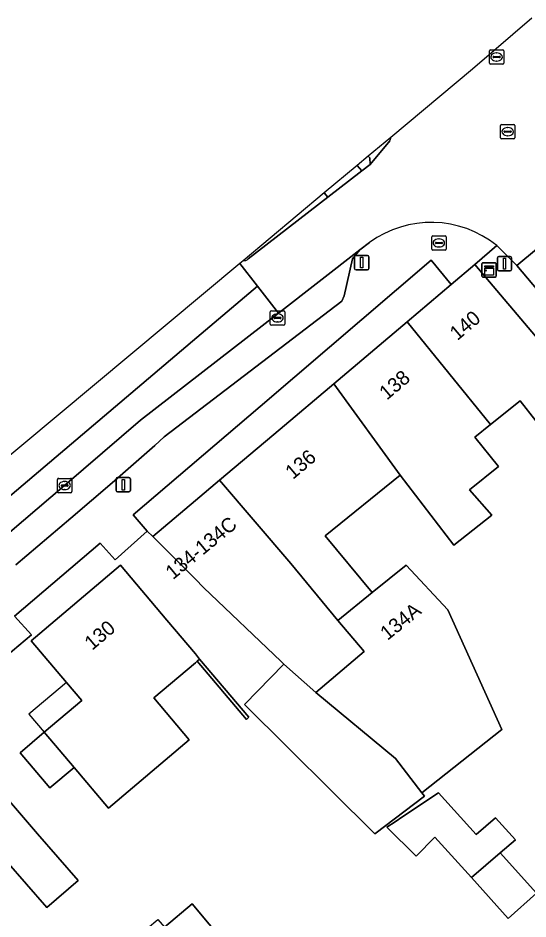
# Model space of a CAD drawing. Extents: x 162172 to 163187, y 382874 to 383685.
# Drawn here: x 162487.7 to 162523.1, y 383338.9 to 383401.6 of the extents above; entities that cross this region are included whole.
import ezdxf

# ---------------------------------------------------------------- set-up
doc = ezdxf.new("R2010")
doc.units = 0
for name, color, linetype in [('IMGEO_Brandkraan', 7, 'Continuous'), ('IMGEO_Erf', 7, 'Continuous'), ('IMGEO_Kast', 7, 'Continuous'), ('IMGEO_Kolk', 7, 'Continuous'), ('IMGEO_Lichtmast', 7, 'Continuous'), ('IMGEO_Muur', 7, 'Continuous'), ('IMGEO_Pand', 7, 'Continuous'), ('IMGEO_Pand_nummerreeks', 7, 'Continuous'), ('IMGEO_Pand_overbouw', 7, 'Continuous'), ('IMGEO_Parkeervlak_open', 7, 'Continuous'), ('IMGEO_Rijbaan_lokaal_gesloten', 7, 'Continuous'), ('IMGEO_Rioolput', 7, 'Continuous'), ('IMGEO_Verkeerseiland_gesloten', 7, 'Continuous'), ('IMGEO_Verkeerseiland_open', 7, 'Continuous'), ('IMGEO_Voetpad_open', 7, 'Continuous')]:
    doc.layers.add(name, color=color, linetype=linetype)

msp = doc.modelspace()

# ---------------------------------------------------------------- linework, layer by layer
at = {"layer": 'IMGEO_Brandkraan'}
for p, q in [((162516.501, 383386.413), (162517.353, 383386.413)), ((162516.426, 383385.487), (162516.426, 383386.339)), ((162516.685, 383385.907), (162516.685, 383385.919)), ((162517.123, 383385.87), (162516.725, 383385.87)), ((162516.728, 383385.956), (162517.126, 383385.956)), ((162516.914, 383386.193), (162516.939, 383386.193)), ((162517.169, 383385.919), (162517.169, 383385.907)), ((162517.427, 383386.339), (162517.427, 383385.487)), ((162517.353, 383385.413), (162516.501, 383385.413)), ((162516.937, 383385.633), (162516.912, 383385.633))]:
    msp.add_line(p, q, dxfattribs=at)
for points in [[(162516.501, 383386.413), (162517.353, 383386.413)], [(162516.426, 383385.487), (162516.426, 383386.339)], [(162517.427, 383386.339), (162517.427, 383385.487)], [(162517.353, 383385.413), (162516.501, 383385.413)]]:
    msp.add_lwpolyline(points, dxfattribs=at)
for centre, radius, start, end in [((162516.503, 383386.337), 0.0765, 91.55205, 178.44795), ((162516.503, 383386.337), 0.0765, 91.55205, 178.44795), ((162517.351, 383386.337), 0.0765, 1.55205, 88.44795), ((162517.351, 383386.337), 0.0765, 1.55205, 88.44795), ((162516.725, 383385.916), 0.0403, 85.87752, 175.75265), ((162516.722, 383385.906), 0.0366, 178.93798, 274.71019), ((162517.126, 383385.913), 0.043, 264.86636, 352.45326), ((162517.13, 383385.918), 0.0386, 1.73085, 96.63898), ((162516.503, 383385.489), 0.0765, 181.55205, 268.44795), ((162516.503, 383385.489), 0.0765, 181.55205, 268.44795), ((162517.351, 383385.489), 0.0765, 271.55205, 358.44795), ((162517.351, 383385.489), 0.0765, 271.55205, 358.44795)]:
    msp.add_arc(centre, radius, start, end, dxfattribs=at)
for centre, major_axis, ratio, start_param, end_param in [((162516.913, 383385.913), (-0.387, 0.002), 0.722429, 4.712389, 7.853982), ((162516.938, 383385.913), (-0.39, 0.002), 0.717154, 1.570796, 4.712389)]:
    msp.add_ellipse(centre, major_axis=major_axis, ratio=ratio, start_param=start_param, end_param=end_param, dxfattribs=at)
at = {"layer": 'IMGEO_Erf'}
for points in [[(162514.719, 383380.429), (162517.788, 383383.021), (162516.381, 383384.728), (162504.504, 383374.543), (162495.688, 383367.015), (162496.66, 383365.876), (162497.039, 383365.491), (162500, 383367.993), (162501.673, 383369.406), (162505.887, 383372.966), (162509.628, 383376.127)], [(162493.954, 383346.606), (162491.568, 383349.429), (162489.89, 383348.011), (162487.823, 383350.458), (162489.498, 383351.878), (162492.105, 383354.084), (162491.038, 383355.349), (162488.584, 383358.252), (162494.787, 383363.495), (162498.015, 383359.676), (162500, 383357.328), (162500.298, 383356.976), (162503.724, 383352.923), (162503.551, 383352.777), (162500.125, 383356.829), (162500, 383356.723), (162497.117, 383354.277), (162499.58, 383351.362)], [(162519.187, 383341.776), (162516.653, 383344.592), (162515.348, 383343.264), (162513.305, 383345.272), (162513.885, 383345.659), (162514.422, 383346.017), (162516.899, 383347.669), (162519.508, 383344.771), (162520.866, 383345.939), (162522.244, 383344.408), (162521.184, 383343.495), (162523.7, 383340.699), (162521.742, 383338.937)], [(162500.266, 383335.557), (162500.462, 383335.333), (162497.535, 383332.877), (162494.528, 383336.46), (162497.382, 383338.856), (162497.848, 383338.323), (162499.778, 383339.943), (162502.141, 383337.128)]]:
    msp.add_lwpolyline(points, close=True, dxfattribs=at)
for points in [[(162525.842, 383370.767), (162522.567, 383374.937), (162520.525, 383373.288), (162519.423, 383372.398), (162521.073, 383370.369), (162519.047, 383368.745), (162520.601, 383366.992), (162517.97, 383364.884), (162514.245, 383369.761), (162509.032, 383365.553), (162512.296, 383361.595), (162514.663, 383363.508), (162517.538, 383360.406), (162521.291, 383352.065), (162515.743, 383347.675), (162515.922, 383347.439), (162512.471, 383344.81), (162503.422, 383353.804), (162506.151, 383356.625), (162505.974, 383356.794), (162500.574, 383361.955), (162500, 383362.529), (162497.039, 383365.491), (162496.66, 383365.876), (162494.431, 383363.864), (162493.381, 383365.045), (162487.439, 383359.96), (162488.604, 383358.667), (162484.189, 383354.943)], [(162485.394, 383349.029), (162489.031, 383344.825), (162491.847, 383341.571), (162489.669, 383339.685), (162486.852, 383342.939)]]:
    msp.add_lwpolyline(points, dxfattribs=at)
at = {"layer": 'IMGEO_Kast'}
for p, q in [((162519.992, 383384.536), (162520.833, 383384.536)), ((162520.833, 383384.536), (162519.992, 383384.536)), ((162519.917, 383383.611), (162519.917, 383384.452)), ((162519.917, 383384.452), (162519.917, 383383.611)), ((162520.917, 383384.461), (162520.917, 383383.62)), ((162520.917, 383383.62), (162520.917, 383384.461)), ((162520.842, 383383.536), (162520.001, 383383.536)), ((162520.001, 383383.536), (162520.842, 383383.536))]:
    msp.add_line(p, q, dxfattribs=at)
for points in [[(162520.112, 383384.326), (162520.712, 383384.326), (162520.712, 383384.241), (162520.112, 383384.241), (162520.112, 383384.326)], [(162520.112, 383384.151), (162520.712, 383384.151), (162520.712, 383383.662), (162520.112, 383383.662), (162520.112, 383384.151)]]:
    msp.add_lwpolyline(points, dxfattribs=at)
msp.add_circle((162520.196, 383384), 0.0377, dxfattribs=at)
for centre, start, end in [((162519.995, 383384.458), 92.4484, 184.28452), ((162519.995, 383384.458), 92.4484, 184.28452), ((162520.839, 383384.458), 2.4484, 94.28452), ((162520.839, 383384.458), 2.4484, 94.28452), ((162519.995, 383383.614), 182.4484, 274.28452), ((162519.995, 383383.614), 182.4484, 274.28452), ((162520.839, 383383.614), 272.4484, 4.28452), ((162520.839, 383383.614), 272.4484, 4.28452)]:
    msp.add_arc(centre, 0.0779, start, end, dxfattribs=at)
at = {"layer": 'IMGEO_Kolk'}
for p, q in [((162505.208, 383380.274), (162505.208, 383381.126)), ((162505.283, 383381.2), (162506.135, 383381.2)), ((162505.51, 383380.743), (162505.908, 383380.743)), ((162505.696, 383380.98), (162505.721, 383380.98)), ((162506.209, 383381.126), (162506.209, 383380.274)), ((162506.135, 383380.2), (162505.283, 383380.2)), ((162505.467, 383380.694), (162505.467, 383380.706)), ((162505.905, 383380.657), (162505.507, 383380.657)), ((162505.719, 383380.42), (162505.694, 383380.42)), ((162505.951, 383380.706), (162505.951, 383380.694)), ((162490.414, 383368.617), (162490.414, 383369.469)), ((162490.489, 383369.543), (162491.341, 383369.543)), ((162491.415, 383369.469), (162491.415, 383368.617)), ((162490.673, 383369.037), (162490.673, 383369.049)), ((162491.111, 383369), (162490.713, 383369)), ((162490.716, 383369.086), (162491.114, 383369.086)), ((162490.902, 383369.323), (162490.927, 383369.323)), ((162491.157, 383369.049), (162491.157, 383369.037)), ((162491.341, 383368.543), (162490.489, 383368.543)), ((162490.925, 383368.763), (162490.9, 383368.763))]:
    msp.add_line(p, q, dxfattribs=at)
for points in [[(162505.208, 383380.274), (162505.208, 383381.126)], [(162505.283, 383381.2), (162506.135, 383381.2)], [(162506.209, 383381.126), (162506.209, 383380.274)], [(162506.135, 383380.2), (162505.283, 383380.2)], [(162490.414, 383368.617), (162490.414, 383369.469)], [(162490.489, 383369.543), (162491.341, 383369.543)], [(162491.415, 383369.469), (162491.415, 383368.617)], [(162491.341, 383368.543), (162490.489, 383368.543)]]:
    msp.add_lwpolyline(points, dxfattribs=at)
for centre, radius, start, end in [((162505.285, 383381.124), 0.0765, 91.55205, 178.44795), ((162505.285, 383381.124), 0.0765, 91.55205, 178.44795), ((162505.507, 383380.703), 0.0403, 85.87752, 175.75265), ((162505.912, 383380.705), 0.0386, 1.73085, 96.63898), ((162506.133, 383381.124), 0.0765, 1.55205, 88.44795), ((162506.133, 383381.124), 0.0765, 1.55205, 88.44795), ((162505.285, 383380.276), 0.0765, 181.55205, 268.44795), ((162505.285, 383380.276), 0.0765, 181.55205, 268.44795), ((162505.504, 383380.693), 0.0366, 178.93798, 274.71019), ((162505.908, 383380.7), 0.043, 264.86636, 352.45326), ((162506.133, 383380.276), 0.0765, 271.55205, 358.44795), ((162506.133, 383380.276), 0.0765, 271.55205, 358.44795), ((162490.491, 383369.467), 0.0765, 91.55205, 178.44795), ((162490.491, 383369.467), 0.0765, 91.55205, 178.44795), ((162491.339, 383369.467), 0.0765, 1.55205, 88.44795), ((162491.339, 383369.467), 0.0765, 1.55205, 88.44795), ((162490.713, 383369.046), 0.0403, 85.87752, 175.75265), ((162490.71, 383369.036), 0.0366, 178.93798, 274.71019), ((162491.114, 383369.043), 0.043, 264.86636, 352.45326), ((162491.118, 383369.048), 0.0386, 1.73085, 96.63898), ((162490.491, 383368.619), 0.0765, 181.55205, 268.44795), ((162490.491, 383368.619), 0.0765, 181.55205, 268.44795), ((162491.339, 383368.619), 0.0765, 271.55205, 358.44795), ((162491.339, 383368.619), 0.0765, 271.55205, 358.44795)]:
    msp.add_arc(centre, radius, start, end, dxfattribs=at)
for centre, major_axis, ratio, start_param, end_param in [((162505.695, 383380.7), (-0.387, 0.002), 0.722429, 4.712389, 7.853982), ((162505.72, 383380.7), (-0.39, 0.002), 0.717154, 1.570796, 4.712389), ((162490.901, 383369.043), (-0.387, 0.002), 0.722429, 4.712389, 7.853982), ((162490.926, 383369.043), (-0.39, 0.002), 0.717154, 1.570796, 4.712389)]:
    msp.add_ellipse(centre, major_axis=major_axis, ratio=ratio, start_param=start_param, end_param=end_param, dxfattribs=at)
at = {"layer": 'IMGEO_Lichtmast'}
for p, q in [((162511.066, 383384.148), (162511.066, 383384.948)), ((162511.066, 383384.948), (162511.066, 383384.148)), ((162511.166, 383385.048), (162511.956, 383385.048)), ((162511.956, 383385.048), (162511.166, 383385.048)), ((162512.056, 383384.948), (162512.056, 383384.148)), ((162512.056, 383384.148), (162512.056, 383384.948)), ((162520.992, 383384.071), (162520.992, 383384.871)), ((162520.992, 383384.871), (162520.992, 383384.071)), ((162521.092, 383384.971), (162521.882, 383384.971)), ((162521.882, 383384.971), (162521.092, 383384.971)), ((162521.982, 383384.871), (162521.982, 383384.071)), ((162521.982, 383384.071), (162521.982, 383384.871)), ((162511.956, 383384.048), (162511.166, 383384.048)), ((162511.166, 383384.048), (162511.956, 383384.048)), ((162521.882, 383383.971), (162521.092, 383383.971)), ((162521.092, 383383.971), (162521.882, 383383.971)), ((162494.494, 383368.697), (162494.494, 383369.497)), ((162494.494, 383369.497), (162494.494, 383368.697)), ((162494.594, 383369.597), (162495.384, 383369.597)), ((162495.384, 383369.597), (162494.594, 383369.597)), ((162495.484, 383369.497), (162495.484, 383368.697)), ((162495.484, 383368.697), (162495.484, 383369.497)), ((162495.384, 383368.597), (162494.594, 383368.597)), ((162494.594, 383368.597), (162495.384, 383368.597))]:
    msp.add_line(p, q, dxfattribs=at)
for points in [[(162511.486, 383384.923), (162511.636, 383384.923), (162511.636, 383384.173), (162511.486, 383384.173), (162511.486, 383384.923)], [(162521.412, 383384.846), (162521.562, 383384.846), (162521.562, 383384.096), (162521.412, 383384.096), (162521.412, 383384.846)], [(162494.914, 383369.472), (162495.064, 383369.472), (162495.064, 383368.722), (162494.914, 383368.722), (162494.914, 383369.472)]]:
    msp.add_lwpolyline(points, dxfattribs=at)
for centre, start, end in [((162511.166, 383384.948), 90, 180), ((162511.166, 383384.948), 90, 180), ((162511.956, 383384.948), 0, 90), ((162511.956, 383384.948), 360, 90), ((162521.092, 383384.871), 90, 180), ((162521.092, 383384.871), 90, 180), ((162521.882, 383384.871), 0, 90), ((162521.882, 383384.871), 360, 90), ((162511.166, 383384.148), 180, 270), ((162511.166, 383384.148), 180, 270), ((162511.956, 383384.148), 270, 0), ((162511.956, 383384.148), 270, 0), ((162521.092, 383384.071), 180, 270), ((162521.092, 383384.071), 180, 270), ((162521.882, 383384.071), 270, 0), ((162521.882, 383384.071), 270, 0), ((162494.594, 383369.497), 90, 180), ((162494.594, 383369.497), 90, 180), ((162495.384, 383369.497), 0, 90), ((162495.384, 383369.497), 360, 90), ((162494.594, 383368.697), 180, 270), ((162494.594, 383368.697), 180, 270), ((162495.384, 383368.697), 270, 0), ((162495.384, 383368.697), 270, 0)]:
    msp.add_arc(centre, 0.1, start, end, dxfattribs=at)
at = {"layer": 'IMGEO_Muur'}
msp.add_lwpolyline([(162500.298, 383356.976), (162500.125, 383356.829), (162503.551, 383352.777), (162503.724, 383352.923)], close=True, dxfattribs=at)
at = {"layer": 'IMGEO_Pand'}
for points in [[(162519.427, 383384.406), (162517.788, 383383.021), (162514.719, 383380.429), (162520.525, 383373.288), (162522.567, 383374.937), (162525.842, 383370.767), (162528.873, 383373.233)], [(162520.525, 383373.288), (162514.719, 383380.429), (162509.628, 383376.127), (162514.245, 383369.761), (162517.97, 383364.884), (162520.601, 383366.992), (162519.047, 383368.745), (162521.073, 383370.369), (162519.423, 383372.398)], [(162509.628, 383376.127), (162505.887, 383372.966), (162501.673, 383369.406), (162506.641, 383363.623), (162509.907, 383359.663), (162512.296, 383361.595), (162509.032, 383365.553), (162514.245, 383369.761)], [(162506.151, 383356.625), (162508.375, 383354.654), (162511.738, 383357.496), (162509.907, 383359.663), (162506.641, 383363.623), (162501.673, 383369.406), (162500, 383367.993), (162497.039, 383365.491), (162500, 383362.529), (162500.574, 383361.955), (162505.974, 383356.794)], [(162500, 383356.723), (162500.125, 383356.829), (162500.298, 383356.976), (162500, 383357.328), (162498.015, 383359.676), (162494.787, 383363.495), (162488.584, 383358.252), (162491.038, 383355.349), (162492.105, 383354.084), (162489.498, 383351.878), (162491.568, 383349.429), (162493.954, 383346.606), (162499.58, 383351.362), (162497.117, 383354.277)], [(162514.663, 383363.508), (162512.296, 383361.595), (162509.907, 383359.663), (162511.738, 383357.496), (162508.375, 383354.654), (162513.921, 383350.066), (162515.743, 383347.675), (162521.291, 383352.065), (162517.538, 383360.406)], [(162506.151, 383356.625), (162503.422, 383353.804), (162512.471, 383344.81), (162515.922, 383347.439), (162515.743, 383347.675), (162513.921, 383350.066), (162508.375, 383354.654)], [(162485.624, 383339.565), (162485.972, 383339.863), (162484.827, 383341.186), (162486.852, 383342.939), (162489.669, 383339.685), (162491.847, 383341.571), (162489.031, 383344.825), (162485.394, 383349.029), (162482.122, 383352.81), (162477.57, 383348.87)], [(162489.498, 383351.878), (162487.823, 383350.458), (162489.89, 383348.011), (162491.568, 383349.429)], [(162519.508, 383344.771), (162516.899, 383347.669), (162514.422, 383346.017), (162513.885, 383345.659), (162513.305, 383345.272), (162515.348, 383343.264), (162516.653, 383344.592), (162519.187, 383341.776), (162521.184, 383343.495), (162522.244, 383344.408), (162520.866, 383345.939)], [(162519.187, 383341.776), (162521.742, 383338.937), (162523.7, 383340.699), (162521.184, 383343.495)], [(162497.848, 383338.323), (162500.266, 383335.557), (162502.141, 383337.128), (162499.778, 383339.943)]]:
    msp.add_lwpolyline(points, close=True, dxfattribs=at)
at = {"layer": 'IMGEO_Pand_overbouw'}
msp.add_lwpolyline([(162492.105, 383354.084), (162491.038, 383355.349), (162488.428, 383353.143), (162489.498, 383351.878)], close=True, dxfattribs=at)
at = {"layer": 'IMGEO_Parkeervlak_open'}
for points in [[(162487.527, 383363.53), (162491.35, 383366.782), (162494.207, 383369.237), (162497.181, 383371.836), (162497.825, 383372.42), (162510.186, 383381.865), (162510.34, 383382.227), (162510.926, 383384.814), (162511.423, 383385.426), (162505.769, 383381.038), (162496.178, 383373.597), (162490.914, 383369.044), (162472.339, 383353.202), (162467.025, 383348.679)], [(162559.274, 383344.525), (162556.137, 383348.129), (162533.509, 383374.259), (162533.37, 383374.43), (162530.552, 383377.712), (162526.275, 383382.59), (162524.132, 383384.985), (162523.71, 383385.48), (162522.345, 383384.348), (162530.852, 383374.243), (162533.366, 383371.252), (162535.503, 383368.71), (162538.127, 383365.59), (162538.316, 383365.365)]]:
    msp.add_lwpolyline(points, dxfattribs=at)
at = {"layer": 'IMGEO_Rijbaan_lokaal_gesloten'}
for points in [[(162523.393, 383401.558), (162519.262, 383397.999), (162513.584, 383393.257)], [(162513.507, 383393.005), (162512.16, 383391.376), (162511.574, 383390.933), (162509.217, 383389.097), (162503.675, 383384.8)], [(162520.947, 383385.736), (162522.345, 383384.348), (162523.71, 383385.48), (162524.132, 383384.985), (162525.302, 383386.015), (162529.068, 383389.331), (162530.178, 383390.309), (162528.583, 383392.222)], [(162503.092, 383384.494), (162504.312, 383382.919), (162505.769, 383381.038), (162511.423, 383385.426), (162512.112, 383385.947)], [(162241.995, 383156.412), (162244.53, 383159.301), (162248.008, 383164.875), (162250.915, 383168.143), (162371.03, 383269.104), (162392.188, 383288.18), (162444.061, 383332.714), (162462.172, 383347.171), (162500.099, 383379.33), (162504.312, 383382.919), (162503.092, 383384.494), (162452.553, 383342.284), (162439.186, 383331.12), (162372.302, 383272.085), (162334.992, 383240.797), (162331.864, 383238.174), (162267.807, 383184.457), (162185.082, 383115.085), (162181.627, 383109.075), (162174.82, 383097.237)], [(162503.315, 383384.68), (162503.092, 383384.494)], [(162445.777, 383331.778), (162464.553, 383346.647), (162467.025, 383348.679), (162472.339, 383353.202), (162490.914, 383369.044), (162496.178, 383373.597), (162505.769, 383381.038), (162504.312, 383382.919), (162500.099, 383379.33), (162462.172, 383347.171), (162444.061, 383332.714), (162392.188, 383288.18), (162371.03, 383269.104), (162250.915, 383168.143), (162248.008, 383164.875), (162244.53, 383159.301), (162241.995, 383156.412)]]:
    msp.add_lwpolyline(points, dxfattribs=at)
for centre, radius, start, end in [((162513.128, 383393.259), 0.456, 326.21711, 359.7716), ((162516.392, 383380.079), 7.263, 51.15624, 126.10757), ((162503.355, 383385.161), 0.482, 265.26464, 311.60526)]:
    msp.add_arc(centre, radius, start, end, dxfattribs=at)
at = {"layer": 'IMGEO_Rioolput'}
for p, q in [((162520.436, 383398.421), (162520.436, 383399.273)), ((162520.511, 383399.347), (162521.363, 383399.347)), ((162520.924, 383399.127), (162520.949, 383399.127)), ((162521.437, 383399.273), (162521.437, 383398.421)), ((162521.363, 383398.347), (162520.511, 383398.347)), ((162520.695, 383398.841), (162520.695, 383398.853)), ((162521.133, 383398.804), (162520.735, 383398.804)), ((162520.738, 383398.89), (162521.136, 383398.89)), ((162520.947, 383398.567), (162520.922, 383398.567)), ((162521.179, 383398.853), (162521.179, 383398.841)), ((162521.211, 383393.228), (162521.211, 383394.08)), ((162521.286, 383394.154), (162522.138, 383394.154)), ((162521.699, 383393.934), (162521.724, 383393.934)), ((162522.212, 383394.08), (162522.212, 383393.228)), ((162521.47, 383393.648), (162521.47, 383393.66)), ((162521.908, 383393.611), (162521.51, 383393.611)), ((162521.513, 383393.697), (162521.911, 383393.697)), ((162521.722, 383393.374), (162521.697, 383393.374)), ((162521.954, 383393.66), (162521.954, 383393.648)), ((162522.138, 383393.154), (162521.286, 383393.154))]:
    msp.add_line(p, q, dxfattribs=at)
for points in [[(162520.436, 383398.421), (162520.436, 383399.273)], [(162520.511, 383399.347), (162521.363, 383399.347)], [(162521.437, 383399.273), (162521.437, 383398.421)], [(162521.363, 383398.347), (162520.511, 383398.347)], [(162521.211, 383393.228), (162521.211, 383394.08)], [(162521.286, 383394.154), (162522.138, 383394.154)], [(162522.212, 383394.08), (162522.212, 383393.228)], [(162522.138, 383393.154), (162521.286, 383393.154)]]:
    msp.add_lwpolyline(points, dxfattribs=at)
for centre, radius, start, end in [((162520.513, 383399.271), 0.0765, 91.55205, 178.44795), ((162520.513, 383399.271), 0.0765, 91.55205, 178.44795), ((162521.361, 383399.271), 0.0765, 1.55205, 88.44795), ((162521.361, 383399.271), 0.0765, 1.55205, 88.44795), ((162520.513, 383398.423), 0.0765, 181.55205, 268.44795), ((162520.513, 383398.423), 0.0765, 181.55205, 268.44795), ((162520.735, 383398.85), 0.0403, 85.87752, 175.75265), ((162520.732, 383398.84), 0.0366, 178.93798, 274.71019), ((162521.136, 383398.847), 0.043, 264.86636, 352.45326), ((162521.14, 383398.852), 0.0386, 1.73085, 96.63898), ((162521.361, 383398.423), 0.0765, 271.55205, 358.44795), ((162521.361, 383398.423), 0.0765, 271.55205, 358.44795), ((162521.288, 383394.078), 0.0765, 91.55205, 178.44795), ((162521.288, 383394.078), 0.0765, 91.55205, 178.44795), ((162522.136, 383394.078), 0.0765, 1.55205, 88.44795), ((162522.136, 383394.078), 0.0765, 1.55205, 88.44795), ((162521.51, 383393.657), 0.0403, 85.87752, 175.75265), ((162521.507, 383393.647), 0.0366, 178.93798, 274.71019), ((162521.911, 383393.654), 0.043, 264.86636, 352.45326), ((162521.915, 383393.659), 0.0386, 1.73085, 96.63898), ((162521.288, 383393.23), 0.0765, 181.55205, 268.44795), ((162521.288, 383393.23), 0.0765, 181.55205, 268.44795), ((162522.136, 383393.23), 0.0765, 271.55205, 358.44795), ((162522.136, 383393.23), 0.0765, 271.55205, 358.44795)]:
    msp.add_arc(centre, radius, start, end, dxfattribs=at)
for centre, major_axis, ratio, start_param, end_param in [((162520.923, 383398.847), (-0.387, 0.002), 0.722429, 4.712389, 7.853982), ((162520.948, 383398.847), (-0.39, 0.002), 0.717154, 1.570796, 4.712389), ((162521.698, 383393.654), (-0.387, 0.002), 0.722429, 4.712389, 7.853982), ((162521.723, 383393.654), (-0.39, 0.002), 0.717154, 1.570796, 4.712389)]:
    msp.add_ellipse(centre, major_axis=major_axis, ratio=ratio, start_param=start_param, end_param=end_param, dxfattribs=at)
at = {"layer": 'IMGEO_Verkeerseiland_gesloten'}
for points in [[(162512.018, 383391.949), (162511.248, 383391.306), (162511.574, 383390.933), (162512.16, 383391.376), (162512.125, 383391.828), (162512.018, 383391.949)], [(162503.675, 383384.8), (162509.217, 383389.097), (162508.954, 383389.39), (162503.315, 383384.68)]]:
    msp.add_lwpolyline(points, dxfattribs=at)
msp.add_arc((162503.355, 383385.161), 0.482, 265.26464, 311.60526, dxfattribs=at)
at = {"layer": 'IMGEO_Verkeerseiland_open'}
msp.add_lwpolyline([(162513.584, 383393.257), (162512.018, 383391.949), (162512.125, 383391.828), (162512.16, 383391.376), (162513.507, 383393.005)], dxfattribs=at)
msp.add_arc((162513.128, 383393.259), 0.456, 326.21711, 359.7716, dxfattribs=at)
at = {"layer": 'IMGEO_Voetpad_open'}
msp.add_lwpolyline([(162508.954, 383389.39), (162509.217, 383389.097), (162511.574, 383390.933), (162511.248, 383391.306)], close=True, dxfattribs=at)
for points in [[(162512.112, 383385.947), (162511.423, 383385.426), (162510.926, 383384.814), (162510.34, 383382.227), (162510.186, 383381.865), (162497.825, 383372.42), (162497.181, 383371.836), (162494.207, 383369.237), (162491.35, 383366.782), (162487.527, 383363.53)], [(162493.381, 383365.045), (162494.431, 383363.864), (162496.66, 383365.876), (162495.688, 383367.015), (162504.504, 383374.543), (162516.381, 383384.728), (162517.788, 383383.021), (162519.427, 383384.406), (162520.947, 383385.736)], [(162538.316, 383365.365), (162538.127, 383365.59), (162537.719, 383365.247), (162535.096, 383368.368), (162535.503, 383368.71), (162533.366, 383371.252), (162532.905, 383370.848), (162530.33, 383373.786), (162530.852, 383374.243), (162522.345, 383384.348), (162520.947, 383385.736), (162519.427, 383384.406), (162528.873, 383373.233), (162533.053, 383368.288), (162536.515, 383364.193), (162554.253, 383343.752)], [(162462.553, 383335.788), (162464.892, 383337.774), (162467.463, 383340.134), (162466.269, 383341.525), (162480.934, 383354.032), (162482.122, 383352.81), (162484.327, 383354.75), (162484.189, 383354.943), (162488.604, 383358.667), (162487.439, 383359.96), (162493.381, 383365.045)]]:
    msp.add_lwpolyline(points, dxfattribs=at)
msp.add_arc((162516.392, 383380.079), 7.263, 51.15624, 126.10757, dxfattribs=at)

# ---------------------------------------------------------------- texts
at = {"layer": 'IMGEO_Pand_nummerreeks'}
for s, rotation, p in [('140', 40.18726, (162518.208, 383379.084)), ('138', 40.19872, (162513.31, 383374.945)), ('136', 40.23883, (162506.78, 383369.425)), ('134-134C', 39.46491, (162498.445, 383362.458)), ('134A', 38.96113, (162513.356, 383358.232)), ('130', 40.20445, (162492.823, 383357.54))]:
    msp.add_text(s, height=1, rotation=rotation, dxfattribs=at).set_placement(p)

doc.saveas('drawing.dxf')
